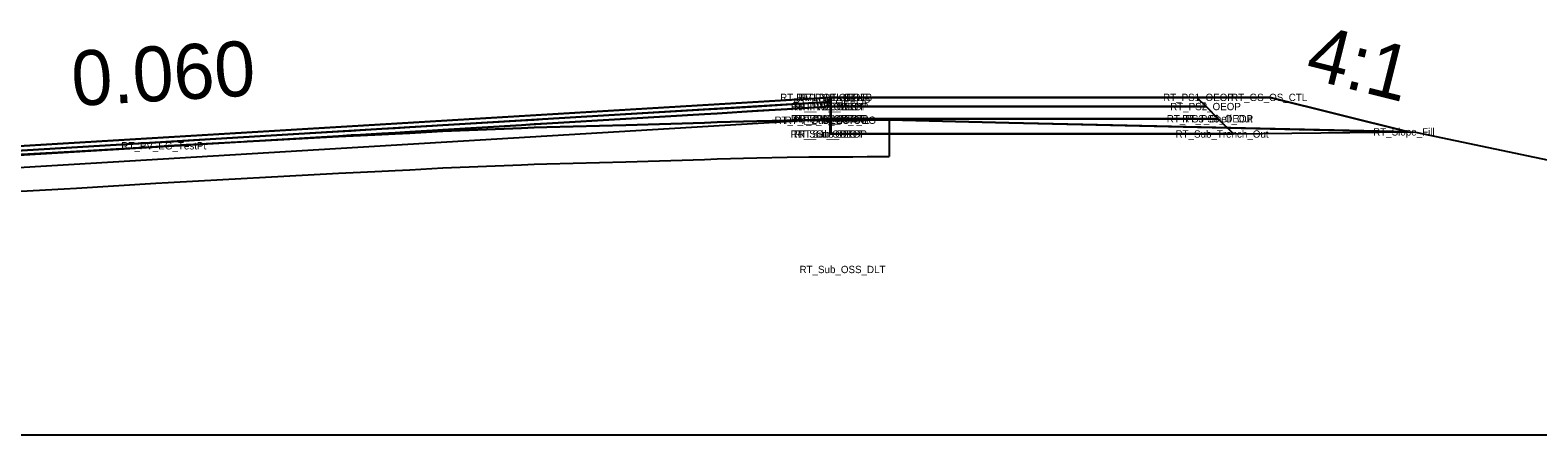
# Model space of a CAD drawing. Extents: x 2177029 to 2201446, y 59897 to 78390.
# Drawn here: x 2199286.88 to 2199328.05, y 68907.31 to 68918.36 of the extents above; entities that cross this region are included whole.
import ezdxf

# ---------------------------------------------------------------- set-up
doc = ezdxf.new("R2010")
doc.units = 0
for name, color, linetype in [('Exist Cross Section Cell', 7, 'Continuous'), ('Exist PHM Roadway Shape', 7, 'Continuous'), ('Exist XS Ground Line', 7, 'Continuous'), ('Old_Level_11', 7, 'Continuous'), ('Prop CMT Conc Surface', 7, 'Continuous'), ('Prop CMT Concrete Structures', 7, 'Continuous'), ('Prop CMT Guardrail Graphics', 7, 'Continuous'), ('Prop CMT Guardrail Widen Shoulder', 7, 'Continuous'), ('Prop CMT Pvmt Course 1', 7, 'Continuous'), ('Prop CMT Pvmt Course 1 CG', 7, 'Continuous'), ('Prop CMT Pvmt Course 2', 7, 'Continuous'), ('Prop CMT Pvmt Course 2 CG', 7, 'Continuous'), ('Prop CMT Pvmt Course 2 Wedge', 7, 'Continuous'), ('Prop CMT Pvmt Course 3', 7, 'Continuous'), ('Prop CMT Pvmt Course 4', 7, 'Continuous'), ('Prop CMT Pvmt Surface', 7, 'Continuous'), ('Prop CMT Pvmt Wedge Surface 1', 7, 'Continuous'), ('Prop CMT Slope Grass', 7, 'Continuous'), ('Prop CMT Subgrade Earthwork', 7, 'Continuous'), ('Prop Hatching', 7, 'Continuous'), ('Prop XS Side Slope Text', 7, 'Continuous'), ('Scratch_Level_0', 7, 'Continuous'), ('Scratch_Level_9', 7, 'Continuous')]:
    doc.layers.add(name, color=color, linetype=linetype)

msp = doc.modelspace()

# ---------------------------------------------------------------- linework, layer by layer
at = {"layer": 'Exist Cross Section Cell'}
msp.add_line((2199242.732, 68907.31), (2199442.732, 68907.31), dxfattribs=at)
at = {"layer": 'Exist XS Ground Line'}
msp.add_lwpolyline([(2199285.643, 68914.91), (2199287.808, 68915.031), (2199288.143, 68915.05), (2199290.306, 68915.18), (2199290.643, 68915.2), (2199292.805, 68915.32), (2199293.143, 68915.339), (2199295.303, 68915.456), (2199295.901, 68915.486), (2199296.481, 68915.513), (2199296.845, 68915.53), (2199297.247, 68915.552), (2199298.144, 68915.6), (2199300.3, 68915.687), (2199300.644, 68915.701), (2199300.987, 68915.71), (2199303.144, 68915.769), (2199305.296, 68915.835), (2199305.643, 68915.846), (2199306.728, 68915.876), (2199307.555, 68915.897), (2199308.143, 68915.902), (2199309.342, 68915.907), (2199309.74, 68915.908), (2199310.34, 68915.916), (2199313.61, 68915.829), (2199324.713, 68915.581), (2199342.389, 68911.864)], dxfattribs=at)
at = {"layer": 'Prop CMT Conc Surface'}
for points in [[(2199308.731, 68916.276), (2199308.731, 68916.526)], [(2199272.732, 68914.241), (2199308.731, 68916.401)], [(2199308.731, 68916.401), (2199308.731, 68916.276), (2199308.731, 68916.276)]]:
    msp.add_lwpolyline(points, dxfattribs=at)
at = {"layer": 'Prop CMT Concrete Structures'}
for p, q in [((2199272.732, 68914.366), (2199308.731, 68916.526)), ((2199308.731, 68916.526), (2199308.741, 68916.527)), ((2199308.741, 68916.527), (2199308.742, 68916.527))]:
    msp.add_line(p, q, dxfattribs=at)
at = {"layer": 'Prop CMT Guardrail Graphics'}
for points in [[(2199308.731, 68915.943), (2199308.731, 68916.526)], [(2199272.732, 68913.783), (2199308.731, 68915.943)]]:
    msp.add_lwpolyline(points, dxfattribs=at)
at = {"layer": 'Prop CMT Pvmt Course 1'}
for points in [[(2199292.805, 68915.321), (2199293.143, 68915.341), (2199295.303, 68915.471), (2199295.644, 68915.491), (2199295.901, 68915.507), (2199296.481, 68915.541), (2199296.845, 68915.563), (2199297.247, 68915.587), (2199297.867, 68915.625), (2199298.144, 68915.641), (2199300.3, 68915.771), (2199300.644, 68915.791), (2199300.987, 68915.812), (2199303.144, 68915.941), (2199305.296, 68916.07), (2199305.643, 68916.091), (2199306.728, 68916.156), (2199307.555, 68916.206), (2199307.829, 68916.222), (2199308.143, 68916.241), (2199308.731, 68916.276)], [(2199308.731, 68916.276), (2199308.731, 68915.943)], [(2199308.731, 68915.943), (2199308.143, 68915.908), (2199308.028, 68915.901), (2199307.829, 68915.899), (2199307.555, 68915.897), (2199306.728, 68915.876), (2199305.643, 68915.846), (2199305.296, 68915.835), (2199303.144, 68915.769), (2199300.987, 68915.71), (2199300.644, 68915.701), (2199300.3, 68915.687), (2199298.144, 68915.6), (2199297.867, 68915.585), (2199297.247, 68915.552), (2199296.845, 68915.53), (2199296.481, 68915.513), (2199295.901, 68915.486), (2199295.644, 68915.474), (2199295.303, 68915.456), (2199293.143, 68915.339), (2199292.805, 68915.32), (2199292.716, 68915.315)], [(2199292.716, 68915.315), (2199292.805, 68915.321)]]:
    msp.add_lwpolyline(points, dxfattribs=at)
at = {"layer": 'Prop CMT Pvmt Course 1 CG'}
for points in [[(2199308.742, 68915.943), (2199319.325, 68915.943)], [(2199308.742, 68915.527), (2199308.742, 68915.943)], [(2199319.325, 68915.943), (2199319.325, 68915.943)], [(2199319.325, 68915.943), (2199319.742, 68915.527)], [(2199319.742, 68915.527), (2199308.742, 68915.527)]]:
    msp.add_lwpolyline(points, dxfattribs=at)
at = {"layer": 'Prop CMT Pvmt Course 2'}
for points in [[(2199308.731, 68915.943), (2199308.742, 68915.943)], [(2199308.731, 68915.526), (2199308.731, 68915.943)], [(2199308.731, 68915.943), (2199308.731, 68915.943), (2199308.731, 68915.526), (2199308.731, 68915.526)], [(2199308.731, 68915.526), (2199308.731, 68915.943)], [(2199308.742, 68915.943), (2199308.742, 68915.527)], [(2199308.742, 68915.527), (2199308.731, 68915.526)]]:
    msp.add_lwpolyline(points, dxfattribs=at)
at = {"layer": 'Prop CMT Pvmt Course 2 CG'}
for points in [[(2199272.732, 68914.366), (2199308.731, 68916.526)], [(2199308.731, 68916.526), (2199308.742, 68916.527)], [(2199308.731, 68916.276), (2199308.731, 68916.526)], [(2199308.731, 68916.526), (2199308.731, 68916.276), (2199308.731, 68916.276), (2199308.731, 68916.401)], [(2199308.742, 68916.527), (2199308.742, 68916.277)], [(2199308.731, 68916.401), (2199272.732, 68914.241)], [(2199308.742, 68916.277), (2199308.731, 68916.276)]]:
    msp.add_lwpolyline(points, dxfattribs=at)
at = {"layer": 'Prop CMT Pvmt Course 2 Wedge'}
for points in [[(2199308.022, 68915.901), (2199308.143, 68915.908)], [(2199308.731, 68915.904), (2199308.143, 68915.902), (2199308.022, 68915.901)], [(2199308.143, 68915.908), (2199308.731, 68915.943)], [(2199308.731, 68915.943), (2199308.731, 68915.904)]]:
    msp.add_lwpolyline(points, dxfattribs=at)
at = {"layer": 'Prop CMT Pvmt Course 3'}
for points in [[(2199308.731, 68915.526), (2199308.717, 68915.904)], [(2199308.731, 68915.526), (2199308.742, 68915.527)], [(2199308.731, 68915.526), (2199308.731, 68915.526)], [(2199308.742, 68915.527), (2199319.742, 68915.527)], [(2199319.742, 68915.527), (2199324.508, 68915.585)]]:
    msp.add_lwpolyline(points, dxfattribs=at)
at = {"layer": 'Prop CMT Pvmt Course 4'}
msp.add_lwpolyline([(2199308.742, 68916.527), (2199318.742, 68916.527)], dxfattribs=at)
at = {"layer": 'Prop CMT Pvmt Surface'}
for points in [[(2199285.643, 68915.016), (2199287.808, 68915.146), (2199288.143, 68915.166), (2199290.306, 68915.296), (2199290.643, 68915.316), (2199292.805, 68915.446), (2199293.143, 68915.466), (2199295.303, 68915.596), (2199295.644, 68915.616), (2199295.901, 68915.632), (2199296.481, 68915.666), (2199296.845, 68915.688), (2199297.247, 68915.712), (2199297.867, 68915.75), (2199298.144, 68915.766), (2199300.3, 68915.896), (2199300.644, 68915.916), (2199300.987, 68915.937), (2199303.144, 68916.066), (2199305.296, 68916.195), (2199305.643, 68916.216), (2199306.728, 68916.281), (2199307.555, 68916.331), (2199307.829, 68916.347), (2199308.143, 68916.366), (2199308.731, 68916.401)], [(2199308.731, 68916.276), (2199308.143, 68916.241), (2199307.829, 68916.222), (2199307.555, 68916.206), (2199306.728, 68916.156), (2199305.643, 68916.091), (2199305.296, 68916.07), (2199303.144, 68915.941), (2199300.987, 68915.812), (2199300.644, 68915.791), (2199300.3, 68915.771), (2199298.144, 68915.641), (2199297.867, 68915.625), (2199297.247, 68915.587), (2199296.845, 68915.563), (2199296.481, 68915.541), (2199295.901, 68915.507), (2199295.644, 68915.491), (2199295.303, 68915.471), (2199293.143, 68915.341), (2199292.805, 68915.321), (2199292.716, 68915.315), (2199290.643, 68915.2), (2199290.306, 68915.18), (2199288.143, 68915.05), (2199287.808, 68915.031), (2199285.643, 68914.91)], [(2199308.731, 68916.401), (2199308.731, 68916.276)]]:
    msp.add_lwpolyline(points, dxfattribs=at)
at = {"layer": 'Prop CMT Pvmt Wedge Surface 1'}
for p, q in [((2199310.34, 68915.916), (2199310.34, 68914.916)), ((2199303.144, 68914.769), (2199305.296, 68914.835)), ((2199305.296, 68914.835), (2199305.643, 68914.846)), ((2199305.643, 68914.846), (2199306.728, 68914.876)), ((2199306.728, 68914.876), (2199307.555, 68914.897)), ((2199307.555, 68914.897), (2199308.143, 68914.902)), ((2199308.143, 68914.902), (2199309.342, 68914.907)), ((2199309.342, 68914.907), (2199309.74, 68914.908)), ((2199309.74, 68914.908), (2199310.34, 68914.916)), ((2199310.34, 68914.916), (2199310.34, 68914.916)), ((2199293.143, 68914.339), (2199295.303, 68914.456)), ((2199295.303, 68914.456), (2199295.901, 68914.486)), ((2199295.901, 68914.486), (2199296.481, 68914.513)), ((2199296.481, 68914.513), (2199296.845, 68914.53)), ((2199296.845, 68914.53), (2199297.247, 68914.552)), ((2199297.247, 68914.552), (2199298.144, 68914.6)), ((2199298.144, 68914.6), (2199300.3, 68914.687)), ((2199300.3, 68914.687), (2199300.644, 68914.701)), ((2199300.644, 68914.701), (2199300.987, 68914.71)), ((2199300.987, 68914.71), (2199303.144, 68914.769)), ((2199285.643, 68913.91), (2199287.808, 68914.031)), ((2199287.808, 68914.031), (2199288.143, 68914.05)), ((2199288.143, 68914.05), (2199290.306, 68914.18)), ((2199290.306, 68914.18), (2199290.643, 68914.2)), ((2199290.643, 68914.2), (2199292.805, 68914.32)), ((2199292.805, 68914.32), (2199293.143, 68914.339))]:
    msp.add_line(p, q, dxfattribs=at)
at = {"layer": 'Prop CMT Slope Grass'}
for points in [[(2199308.731, 68916.276), (2199308.742, 68916.277)], [(2199308.731, 68915.943), (2199308.731, 68916.276)], [(2199308.731, 68915.943), (2199308.731, 68915.943), (2199308.731, 68916.276), (2199308.731, 68916.276)], [(2199308.731, 68916.276), (2199308.731, 68915.943)], [(2199308.742, 68916.277), (2199308.742, 68915.943)], [(2199308.742, 68915.943), (2199308.731, 68915.943)]]:
    msp.add_lwpolyline(points, dxfattribs=at)
at = {"layer": 'Prop CMT Subgrade Earthwork'}
for points in [[(2199308.731, 68916.276), (2199308.731, 68916.526)], [(2199272.732, 68914.116), (2199308.731, 68916.276)]]:
    msp.add_lwpolyline(points, dxfattribs=at)
at = {"layer": 'Prop Hatching'}
msp.add_lwpolyline([(2199318.742, 68916.527), (2199320.742, 68916.527), (2199324.508, 68915.585)], dxfattribs=at)
at = {"layer": 'Prop XS Side Slope Text'}
msp.add_lwpolyline([(2199285.643, 68914.91), (2199287.808, 68915.031), (2199288.143, 68915.05), (2199290.306, 68915.18), (2199290.643, 68915.2), (2199292.805, 68915.32), (2199293.143, 68915.339), (2199295.303, 68915.456), (2199295.901, 68915.486), (2199296.481, 68915.513), (2199296.845, 68915.53), (2199297.247, 68915.552), (2199298.144, 68915.6), (2199300.3, 68915.687), (2199300.644, 68915.701), (2199300.987, 68915.71), (2199303.144, 68915.769), (2199305.296, 68915.835), (2199305.643, 68915.846), (2199306.728, 68915.876), (2199307.555, 68915.897), (2199308.143, 68915.902), (2199308.717, 68915.904), (2199309.342, 68915.907), (2199309.74, 68915.908), (2199310.34, 68915.916), (2199313.61, 68915.829), (2199324.508, 68915.585), (2199320.742, 68916.527), (2199318.742, 68916.527), (2199308.742, 68916.527), (2199272.732, 68914.366)], dxfattribs=at)
msp.add_lwpolyline([(2199319.742, 68915.527), (2199324.508, 68915.585), (2199313.61, 68915.829), (2199310.34, 68915.916), (2199309.74, 68915.908), (2199309.342, 68915.907), (2199308.717, 68915.904), (2199308.731, 68915.526)], close=True, dxfattribs=at)
at = {"layer": 'Scratch_Level_0'}
for points in [[(2199308.742, 68916.277), (2199318.992, 68916.277), (2199319.325, 68915.943)], [(2199308.742, 68915.943), (2199308.742, 68916.277)], [(2199319.325, 68915.943), (2199308.742, 68915.943)]]:
    msp.add_lwpolyline(points, dxfattribs=at)
at = {"layer": 'Scratch_Level_9'}
for points in [[(2199308.742, 68916.527), (2199318.742, 68916.527), (2199318.992, 68916.277)], [(2199308.742, 68916.277), (2199308.742, 68916.527)], [(2199318.992, 68916.277), (2199308.742, 68916.277)]]:
    msp.add_lwpolyline(points, dxfattribs=at)

# ---------------------------------------------------------------- texts
at = {"layer": 'Exist PHM Roadway Shape'}
for s, p in [('RT_PV1_OTL SE LB', (2199307.36, 68916.427)), ('RT_PV1_OEEOP', (2199307.714, 68916.301)), ('RT_PV1_OEOT', (2199307.801, 68916.426)), ('RT_PV1_OTL', (2199307.909, 68916.427)), ('RT_PS1_OEOP', (2199317.818, 68916.427)), ('RT_GS_OS_CTL', (2199319.674, 68916.427)), ('RT_PV_Sub_Tie_Out', (2199307.207, 68915.804)), ('RT_PV2_OEEOP', (2199307.657, 68916.176)), ('RT_PV3_OEEOP', (2199307.657, 68915.843)), ('RT_PV2_OEOT', (2199307.744, 68916.176)), ('RT_PV3_OEOT', (2199307.744, 68915.843)), ('RT_PV2_OTL', (2199307.852, 68916.177)), ('RT_PV3_OTL', (2199307.852, 68915.843)), ('RT_PS3_Shelf_Out', (2199317.919, 68915.843)), ('RT_PS2_OEOP', (2199318.011, 68916.177)), ('RT_PS3_OEOP', (2199318.344, 68915.843)), ('RT_PV_OEEOP_EG', (2199307.481, 68915.804)), ('RT_Sub_OEEOP', (2199307.648, 68915.426)), ('RT_Sub_OEOT', (2199307.735, 68915.426)), ('RT_Sub_OTL', (2199307.843, 68915.427)), ('RT_Sub_Trench_Out', (2199318.158, 68915.427)), ('RT_Slope_Fill', (2199323.555, 68915.485)), ('RT_PV_EG_TestPt', (2199289.368, 68915.105)), ('RT_Sub_OSS_DLT', (2199307.889, 68911.727))]:
    msp.add_text(s, height=0.2, dxfattribs=at).set_placement(p)
at = {"layer": 'Old_Level_11'}
msp.add_text('0.060', height=1.5, rotation=3.4337, dxfattribs=at).set_placement((2199288.051, 68916.287))
at = {"layer": 'Prop CMT Guardrail Widen Shoulder'}
msp.add_text('4:1', height=1.5, rotation=345.957, dxfattribs=at).set_placement((2199321.654, 68917.072))

doc.saveas('drawing.dxf')
